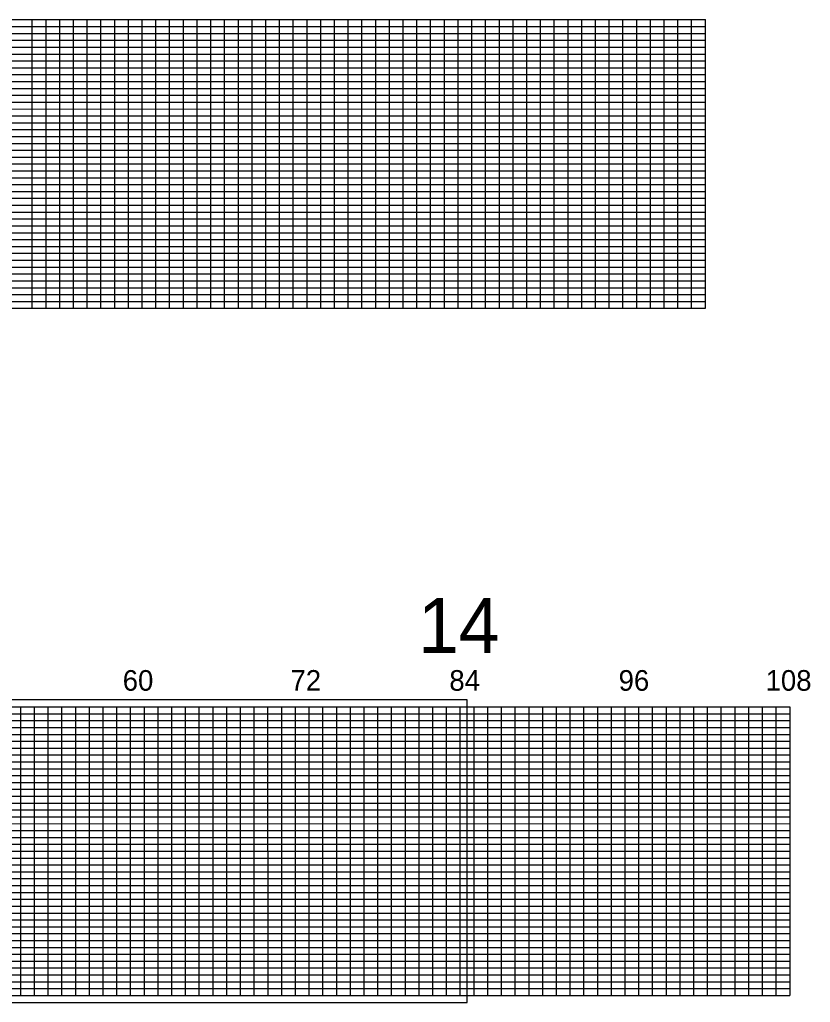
# Model space of a CAD drawing. Extents: x 1914168 to 1925341, y 720939 to 777401.
# Drawn here: x 1917047 to 1919925, y 743439 to 747014 of the extents above; entities that cross this region are included whole.
import ezdxf

# ---------------------------------------------------------------- set-up
doc = ezdxf.new("R2010")
doc.units = 0
for name, color, linetype in [('RD_PD_ALT1_CL', 7, 'Continuous'), ('RD_PD_WallFill', 7, 'Continuous'), ('RD_SHT_IplotShp', 7, 'Continuous')]:
    doc.layers.add(name, color=color, linetype=linetype)

msp = doc.modelspace()

# ---------------------------------------------------------------- linework, layer by layer
at = {"layer": 'RD_PD_WallFill'}
for p, q in [((1914193.1, 747014.1), (1919543.1, 747014.2)), ((1917093.1, 745964.2), (1917093.1, 747014.2)), ((1917143.1, 745964.2), (1917143.1, 747014.2)), ((1917193.1, 745964.2), (1917193.1, 747014.2)), ((1917243.1, 745964.2), (1917243.1, 747014.2)), ((1917293.1, 745964.1), (1917293.1, 747014.2)), ((1917343.1, 745964.2), (1917343.1, 747014.2)), ((1917393.1, 745964.2), (1917393.1, 747014.2)), ((1917443.1, 745964.2), (1917443.1, 747014.2)), ((1917493.1, 745964.2), (1917493.1, 747014.2)), ((1917543.1, 745964.2), (1917543.1, 747014.2)), ((1917593.1, 745964.1), (1917593.1, 747014.2)), ((1917643.1, 745964.1), (1917643.1, 747014.2)), ((1917693.1, 745964.2), (1917693.1, 747014.2)), ((1917743.1, 745964.2), (1917743.1, 747014.2)), ((1917793.1, 745964.2), (1917793.1, 747014.2)), ((1917843.1, 745964.2), (1917843.1, 747014.2)), ((1917893.1, 745964.2), (1917893.1, 747014.2)), ((1917943.1, 745964.2), (1917943.1, 747014.2)), ((1917993.1, 745964.2), (1917993.1, 747014.2)), ((1918043.1, 745964.2), (1918043.1, 747014.2)), ((1918093.1, 745964.2), (1918093.1, 747014.2)), ((1918143.1, 745964.2), (1918143.1, 747014.2)), ((1918193.1, 745964.2), (1918193.1, 747014.2)), ((1918243.1, 745964.2), (1918243.1, 747014.2)), ((1918293.1, 745964.2), (1918293.1, 747014.2)), ((1918343.1, 745964.2), (1918343.1, 747014.2)), ((1918393.1, 745964.2), (1918393.1, 747014.2)), ((1918443.1, 745964.2), (1918443.1, 747014.2)), ((1918493.1, 745964.2), (1918493.1, 747014.2)), ((1918543.1, 745964.2), (1918543.1, 747014.2)), ((1918593.1, 745964.2), (1918593.1, 747014.2)), ((1918643.1, 745964.2), (1918643.1, 747014.2)), ((1918693.1, 745964.2), (1918693.1, 747014.2)), ((1918743.1, 745964.2), (1918743.1, 747014.2)), ((1918793.1, 745964.2), (1918793.1, 747014.2)), ((1918843.1, 745964.2), (1918843.1, 747014.2)), ((1918893.1, 745964.2), (1918893.1, 747014.2)), ((1918943.1, 745964.2), (1918943.1, 747014.2)), ((1918993.1, 745964.2), (1918993.1, 747014.2)), ((1919043.1, 745964.2), (1919043.1, 747014.2)), ((1919093.1, 745964.2), (1919093.1, 747014.2)), ((1919143.1, 745964.2), (1919143.1, 747014.2)), ((1919193.1, 745964.2), (1919193.1, 747014.2)), ((1919243.1, 745964.2), (1919243.1, 747014.2)), ((1919293.1, 745964.2), (1919293.1, 747014.2)), ((1919343.1, 745964.2), (1919343.1, 747014.2)), ((1919393.1, 745964.2), (1919393.1, 747014.2)), ((1919443.1, 745964.2), (1919443.1, 747014.2)), ((1919493.1, 745964.2), (1919493.1, 747014.2)), ((1919543.1, 745964.2), (1919543.1, 747014.2)), ((1914643, 746989.1), (1919543.1, 746989.1)), ((1914643, 746964.1), (1919543.1, 746964.1)), ((1914643, 746939.1), (1919543.1, 746939.1)), ((1914643, 746914.2), (1919543.1, 746914.1)), ((1914193.1, 746864.1), (1919543.1, 746864.1)), ((1914643, 746889.1), (1919543.1, 746889.2)), ((1914193.1, 746839.1), (1919543.1, 746839.1)), ((1914193, 746814.1), (1919543.1, 746814.2)), ((1914193.1, 746789.2), (1919543.1, 746789.1)), ((1914193.1, 746764.2), (1919543.1, 746764.2)), ((1914193.1, 746739.1), (1919543.1, 746739.1)), ((1914193.1, 746714.1), (1919543.1, 746714.1)), ((1914193, 746689.2), (1919543.1, 746689.1)), ((1914193, 746664.1), (1919543.1, 746664.1)), ((1914193.1, 746639.2), (1919543.1, 746639.1)), ((1914193.1, 746614.1), (1919543.1, 746614.1)), ((1914193.1, 746589.1), (1919543.1, 746589.2)), ((1914193, 746539.1), (1919543.1, 746539.2)), ((1914193.1, 746564.1), (1919543.1, 746564.1)), ((1914193.1, 746514.1), (1919543.1, 746514.1)), ((1914193.1, 746489.1), (1919543.1, 746489.1)), ((1914193.1, 746464.2), (1919543.1, 746464.1)), ((1914193.1, 746439.1), (1919543.1, 746439.1)), ((1914193, 746414.1), (1919543.1, 746414.1)), ((1914193, 746389.1), (1919543.1, 746389.1)), ((1914193.1, 746364.1), (1919543.1, 746364.2)), ((1914193.1, 746339.1), (1919543.1, 746339.1)), ((1914193.1, 746314.1), (1919543.1, 746314.1)), ((1914193.1, 746289.1), (1919543.1, 746289.1)), ((1914193, 746264.1), (1919543.1, 746264.1)), ((1914193.1, 746239.1), (1919543.1, 746239.1)), ((1914193.1, 746214.1), (1919543.1, 746214.1)), ((1914193.1, 746189.1), (1919543.1, 746189.1)), ((1914193.1, 746164.1), (1919543.1, 746164.1)), ((1914193, 746139.1), (1919543.1, 746139.1)), ((1914193.1, 746114.1), (1919543.1, 746114.1)), ((1914193.1, 746089.1), (1919543.1, 746089.1)), ((1914193.1, 746064.1), (1919543.1, 746064.1)), ((1914193.1, 746039.1), (1919543.1, 746039.1)), ((1914193, 746014.1), (1919543.1, 746014.1)), ((1914193.1, 745964.1), (1919543.1, 745964.1)), ((1914243, 745989.1), (1919543.1, 745989.1)), ((1914501, 744514.1), (1919851, 744514.2)), ((1917051, 743464.2), (1917051, 744514.2)), ((1917101, 743464.2), (1917101, 744514.2)), ((1917151, 743464.2), (1917151, 744514.2)), ((1917201, 743464.2), (1917201, 744514.2)), ((1917251, 743464.2), (1917251, 744514.2)), ((1917301, 743464.2), (1917301, 744514.2)), ((1917351, 743464.2), (1917351, 744514.2)), ((1917401, 743464.2), (1917401, 744514.2)), ((1917451, 743464.2), (1917451, 744514.2)), ((1917501, 743464.2), (1917501, 744514.2)), ((1917551, 743464.2), (1917551, 744514.2)), ((1917601.1, 743464.1), (1917601, 744514.2)), ((1917651, 743464.2), (1917651.1, 744514.2)), ((1917701, 743464.2), (1917701, 744514.2)), ((1917751, 743464.2), (1917751, 744514.2)), ((1917801.1, 743464.2), (1917801, 744514.2)), ((1917851.1, 743464.2), (1917851.1, 744514.2)), ((1917901, 743464.1), (1917901, 744514.2)), ((1917951.1, 743464.1), (1917951, 744514.2)), ((1918001.1, 743464.2), (1918001.1, 744514.2)), ((1918051, 743464.2), (1918051.1, 744514.2)), ((1918101, 743464.2), (1918101, 744514.2)), ((1918151.1, 743464.2), (1918151.1, 744514.2)), ((1918201.1, 743464.2), (1918201.1, 744514.2)), ((1918251.1, 743464.2), (1918251.1, 744514.2)), ((1918301.1, 743464.2), (1918301.1, 744514.2)), ((1918351.1, 743464.2), (1918351.1, 744514.2)), ((1918401.1, 743464.2), (1918401.1, 744514.2)), ((1918451.1, 743464.2), (1918451.1, 744514.2)), ((1918501.1, 743464.2), (1918501.1, 744514.2)), ((1918551.1, 743464.2), (1918551.1, 744514.2)), ((1918601.1, 743464.2), (1918601.1, 744514.2)), ((1918651.1, 743464.2), (1918651.1, 744514.2)), ((1918701.1, 743464.2), (1918701.1, 744514.2)), ((1918751.1, 743464.2), (1918751.1, 744514.2)), ((1918801.1, 743464.2), (1918801.1, 744514.2)), ((1918851.1, 743464.2), (1918851.1, 744514.2)), ((1918901.1, 743464.2), (1918901.1, 744514.2)), ((1918951.1, 743464.2), (1918951.1, 744514.2)), ((1919001.1, 743464.2), (1919001.1, 744514.2)), ((1919051.1, 743464.2), (1919051.1, 744514.2)), ((1919101.1, 743464.2), (1919101.1, 744514.2)), ((1919151.1, 743464.2), (1919151.1, 744514.2)), ((1919201.1, 743464.2), (1919201.1, 744514.2)), ((1919251.1, 743464.2), (1919251.1, 744514.2)), ((1919301.1, 743464.2), (1919301.1, 744514.2)), ((1919351.1, 743464.2), (1919351.1, 744514.2)), ((1919401.1, 743464.2), (1919401.1, 744514.2)), ((1919451.1, 743464.2), (1919451.1, 744514.2)), ((1919501.1, 743464.2), (1919501.1, 744514.2)), ((1919551.1, 743464.2), (1919551.1, 744514.2)), ((1919601.1, 743464.2), (1919601.1, 744514.2)), ((1919651.1, 743464.2), (1919651.1, 744514.2)), ((1919701.1, 743464.2), (1919701.1, 744514.2)), ((1919751.1, 743464.2), (1919751.1, 744514.2)), ((1919801.1, 743464.2), (1919801.1, 744514.2)), ((1919851.1, 743464.2), (1919851.1, 744514.2)), ((1914951, 744489.1), (1919851, 744489.1)), ((1914951, 744464.1), (1919851, 744464.1)), ((1914951, 744439.1), (1919851, 744439.1)), ((1914951, 744414.2), (1919851, 744414.1)), ((1914951, 744389.1), (1919851, 744389.2)), ((1914501, 744364.1), (1919851, 744364.1)), ((1914501, 744339.1), (1919851, 744339.1)), ((1914501, 744314.1), (1919851, 744314.2)), ((1914501, 744289.2), (1919851, 744289.1)), ((1914501, 744264.2), (1919851, 744264.2)), ((1914501, 744239.1), (1919851, 744239.1)), ((1914501, 744214.1), (1919851, 744214.1)), ((1914501, 744189.2), (1919851, 744189.1)), ((1914501, 744164.1), (1919851, 744164.1)), ((1914501, 744139.2), (1919851, 744139.1)), ((1914501, 744114.1), (1919851, 744114.1)), ((1914501, 744089.1), (1919851, 744089.2)), ((1914501, 744064.1), (1919851, 744064.1)), ((1914501, 744039.1), (1919851, 744039.2)), ((1914501, 744014.1), (1919851, 744014.1)), ((1914501, 743989.1), (1919851, 743989.1)), ((1914501, 743964.2), (1919851, 743964.1)), ((1914501, 743939.1), (1919851, 743939.1)), ((1914501, 743914.1), (1919851, 743914.1)), ((1914501, 743889.1), (1919851, 743889.1)), ((1914501, 743864.1), (1919851, 743864.2)), ((1914501, 743839.1), (1919851, 743839.1)), ((1914501, 743814.1), (1919851, 743814.1)), ((1914501, 743789.1), (1919851, 743789.1)), ((1914501, 743764.1), (1919851, 743764.1)), ((1914501, 743739.1), (1919851, 743739.1)), ((1914501, 743714.1), (1919851, 743714.1)), ((1914501, 743689.1), (1919851, 743689.1)), ((1914501, 743664.1), (1919851, 743664.1)), ((1914501, 743639.1), (1919851, 743639.1)), ((1914501, 743614.1), (1919851, 743614.1)), ((1914501, 743589.1), (1919851, 743589.1)), ((1914501, 743564.1), (1919851, 743564.1)), ((1914501, 743539.1), (1919851, 743539.1)), ((1914501, 743514.1), (1919851, 743514.1)), ((1914501, 743464.1), (1919851, 743464.1)), ((1914551, 743489.1), (1919851, 743489.1))]:
    msp.add_line(p, q, dxfattribs=at)
at = {"layer": 'RD_SHT_IplotShp'}
msp.add_lwpolyline([(1914476, 743439.1), (1918676, 743439.1), (1918676, 744539.1), (1914476, 744539.1)], close=True, dxfattribs=at)

# ---------------------------------------------------------------- texts
at = {"layer": 'RD_PD_ALT1_CL'}
msp.add_text('14', height=200, dxfattribs=at).set_placement((1918496.7, 744710))
at = {"layer": 'RD_PD_WallFill'}
for s, p in [('60', (1917422.2, 744572.8)), ('72', (1918032.9, 744572.8)), ('84', (1918611.1, 744572.8)), ('96', (1919227.2, 744572.8)), ('108', (1919762.2, 744572.8))]:
    msp.add_text(s, height=75, dxfattribs=at).set_placement(p)

doc.saveas('drawing.dxf')
